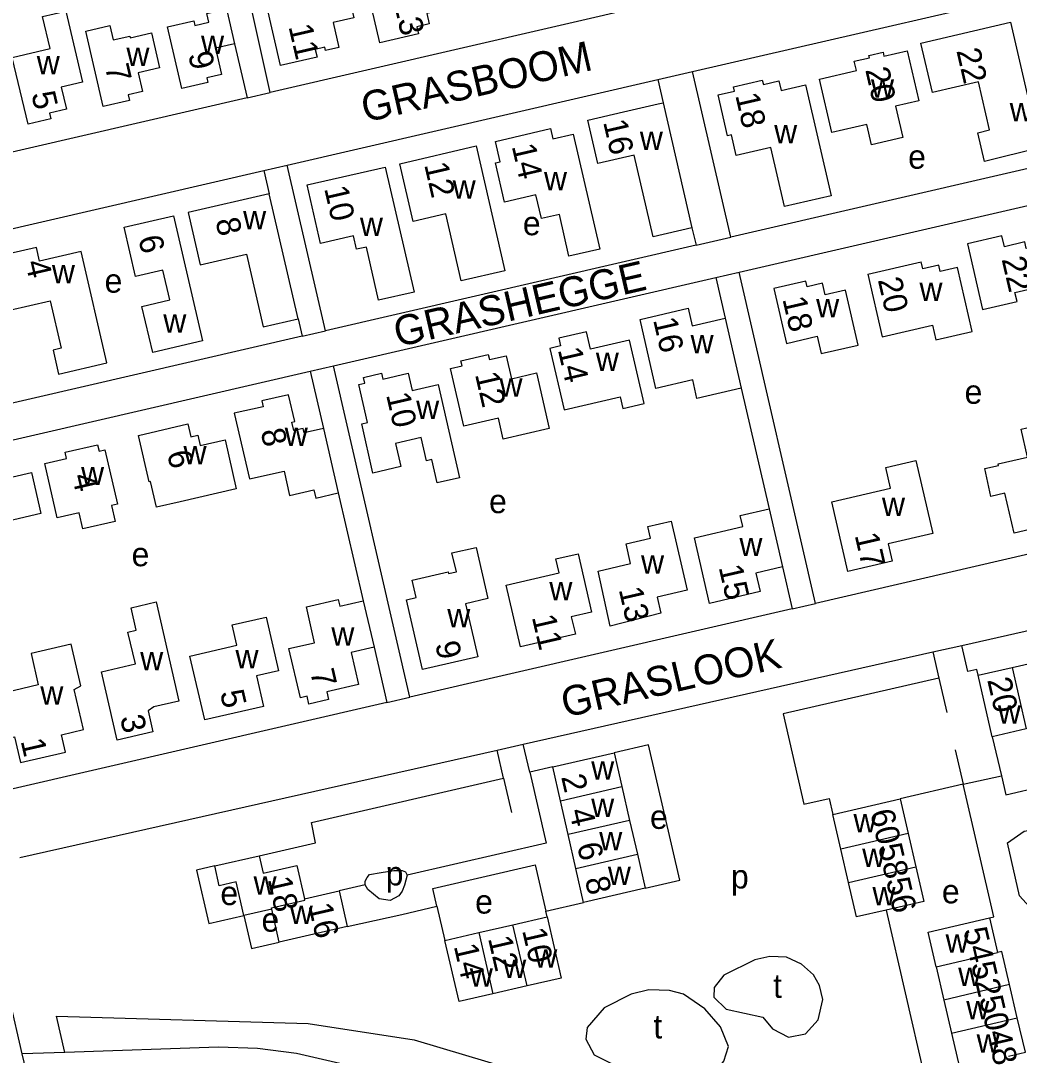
# Model space of a CAD drawing. Extents: x 155696 to 157795, y 382328 to 384028.
# Drawn here: x 157117.5 to 157284.9, y 383139.6 to 383313 of the extents above; entities that cross this region are included whole.
import ezdxf

# ---------------------------------------------------------------- set-up
doc = ezdxf.new("R2010")
doc.units = 0
for name, color, linetype in [('BLT_Basislijn', 7, 'Continuous'), ('BLT_Bebouwing', 7, 'Continuous'), ('BLT_Centroide', 7, 'Continuous'), ('BLT_Huisnummer', 7, 'Continuous'), ('BLT_Huisnummer_ tussenligend', 7, 'Continuous'), ('BLT_Onderverdeling_panden', 7, 'Continuous'), ('BLT_Straatnaam', 7, 'Continuous')]:
    doc.layers.add(name, color=color, linetype=linetype)

msp = doc.modelspace()

# ---------------------------------------------------------------- linework, layer by layer
at = {"layer": 'BLT_Basislijn'}
for p, q in [((157224.34, 383303.11), (157230.18, 383304.46)), ((157155.49, 383300.03), (157159.39, 383300.93)), ((157158.3, 383287.85), (157162.2, 383288.76)), ((157230.75, 383275.34), (157236.6, 383276.69)), ((157234.05, 383269.94), (157237.95, 383270.84)), ((157164.72, 383260.09), (157168.62, 383260.99)), ((157166.07, 383254.24), (157169.96, 383255.14)), ((157246.88, 383214.4), (157250.77, 383215.3)), ((157275.31, 383208.27), (157300.88, 383214.03)), ((157270.44, 383207.17), (157275.31, 383208.27)), ((157276.32, 383203.89), (157275.31, 383208.27)), ((157201.79, 383191.71), (157270.44, 383207.17)), ((157270.44, 383207.17), (157271.45, 383202.77)), ((157277.81, 383204.24), (157276.32, 383203.89)), ((157278.04, 383203.25), (157277.81, 383204.24)), ((157271.45, 383202.77), (157245.33, 383196.77)), ((157271.45, 383202.77), (157272.77, 383197.01)), ((157178.9, 383198.7), (157182.79, 383199.6)), ((157245.33, 383196.77), (157248.8, 383181.66)), ((157197.4, 383190.72), (157201.79, 383191.71)), ((157202.87, 383187), (157201.79, 383191.71)), ((157280.41, 383192.96), (157281.93, 383186.38)), ((157117.41, 383172.7), (157197.4, 383190.72)), ((157198.49, 383185.99), (157197.4, 383190.72)), ((157222.8, 383191.61), (157217, 383190.27)), ((157228.02, 383168.9), (157222.8, 383191.61)), ((157274.21, 383190.74), (157275.53, 383184.98)), ((157282.65, 383183.23), (157305.41, 383188.47)), ((157206.73, 383187.89), (157202.87, 383187)), ((157166.27, 383178.58), (157198.49, 383185.99)), ((157198.49, 383185.99), (157199.81, 383180.23)), ((157275.53, 383184.98), (157264.98, 383182.54)), ((157275.53, 383184.98), (157281.93, 383186.38)), ((157280.66, 383162.77), (157275.53, 383184.98)), ((157281.93, 383186.38), (157282.65, 383183.23)), ((157248.8, 383181.66), (157253.05, 383182.63)), ((157253.05, 383182.63), (157253.67, 383179.91)), ((157166.95, 383175.19), (157166.27, 383178.58)), ((157157.52, 383173.02), (157166.95, 383175.19)), ((157150.07, 383171.3), (157147.03, 383170.61)), ((157186.63, 383167.53), (157203.76, 383171.49)), ((157203.76, 383171.49), (157205.55, 383163.72)), ((157147.03, 383170.61), (157149.09, 383161.66)), ((157175.3, 383168.14), (157170.91, 383167.13)), ((157187.32, 383164.54), (157186.63, 383167.53)), ((157222.23, 383167.57), (157228.02, 383168.9)), ((157117.82, 383139.81), (157111.96, 383165.17)), ((157181.41, 383163.18), (157187.32, 383164.54)), ((157187.32, 383164.54), (157188.64, 383158.81)), ((157205.55, 383163.72), (157211.91, 383165.18)), ((157262.64, 383163.9), (157269.01, 383136.17)), ((157149.09, 383161.66), (157154.94, 383163)), ((157154.94, 383163), (157156.22, 383157.44)), ((157172.3, 383161.13), (157181.41, 383163.18)), ((157205.77, 383162.76), (157205.55, 383163.72)), ((157279.91, 383162.6), (157280.66, 383162.77)), ((157156.22, 383157.44), (157160.89, 383158.52)), ((157124.94, 383140.05), (157123.54, 383146.13)), ((157124.94, 383140.05), (157117.82, 383139.81)), ((157118.96, 383134.84), (157117.82, 383139.81))]:
    msp.add_line(p, q, dxfattribs=at)
for points in [[(157214.18, 383354.66), (157223.47, 383315.74), (157159.39, 383300.93), (157151.43, 383336.7)], [(157230.18, 383304.46), (157302.05, 383321.06)], [(157153.4, 383309.09), (157155.49, 383300.03), (157091.41, 383285.23)], [(157236.6, 383276.69), (157230.18, 383304.46)], [(157162.2, 383288.75), (157224.34, 383303.11), (157225.24, 383299.21)], [(157308.46, 383293.29), (157236.6, 383276.69)], [(157230.07, 383278.26), (157230.75, 383275.34), (157168.62, 383260.99), (157162.2, 383288.75)], [(157094.22, 383273.05), (157158.3, 383287.85), (157159.21, 383283.96)], [(157237.95, 383270.84), (157309.81, 383287.44)], [(157169.96, 383255.14), (157234.05, 383269.94)], [(157234.05, 383269.94), (157235.62, 383263.12)], [(157250.77, 383215.3), (157237.95, 383270.84)], [(157164.04, 383263.01), (157164.72, 383260.09), (157100.64, 383245.28)], [(157101.99, 383239.44), (157166.07, 383254.24)], [(157166.07, 383254.24), (157168.28, 383244.63)], [(157245.26, 383221.42), (157246.88, 383214.4), (157182.79, 383199.6), (157169.96, 383255.14)], [(157238.34, 383251.37), (157243.01, 383231.15)], [(157170.77, 383233.83), (157174.96, 383215.75)], [(157322.64, 383231.91), (157250.77, 383215.3)], [(157176.79, 383207.96), (157178.9, 383198.7)], [(157178.9, 383198.7), (157114.81, 383183.9)], [(157202.87, 383187), (157205.61, 383175.11), (157182.32, 383169.75)], [(157284.98, 383166.29), (157282.93, 383175.16), (157285.75, 383177.1), (157287.16, 383177.36), (157290.54, 383176.56), (157293.33, 383173.77), (157293.92, 383171.91), (157293.52, 383166.12), (157292.67, 383164.35), (157290.49, 383162.88), (157287.76, 383163.22), (157284.98, 383166.29)], [(157175.3, 383168.14), (157175.3, 383168.75), (157175.6, 383169.38), (157176.04, 383169.85), (157177.98, 383170.22), (157180.09, 383170.53), (157181.51, 383170.52), (157182.04, 383170.29), (157182.32, 383169.75)], [(157182.32, 383169.75), (157181.89, 383168.1), (157181.5, 383167.08), (157180.96, 383166.3), (157179.46, 383165.52), (157177.62, 383165.76), (157175.72, 383167.33), (157175.3, 383168.14)], [(157123.54, 383146.13), (157165.71, 383144.89), (157183.5, 383142.13), (157200.18, 383137.2), (157235.58, 383131.54), (157251.21, 383129.94), (157257.67, 383129.07), (157261.63, 383127.15), (157269.74, 383120.29), (157297.41, 383095.23)], [(157250.28, 383126.07), (157247.36, 383126.69), (157243.18, 383127.21), (157231.56, 383128.31), (157202.23, 383131.88), (157178.54, 383136.45), (157163.78, 383139.88), (157157.25, 383140.71), (157150.71, 383140.93), (157124.94, 383140.05)]]:
    msp.add_lwpolyline(points, dxfattribs=at)
for points in [[(157240.61, 383155.57), (157235.42, 383152.97), (157233.77, 383150.95), (157233.71, 383149.28), (157235.81, 383147.32), (157241.93, 383145.94), (157243.58, 383143.97), (157246.22, 383142.6), (157249.07, 383143.16), (157251.22, 383145.52), (157252, 383148.92), (157251.46, 383151.24), (157250.44, 383153.05), (157248.42, 383154.82), (157245.92, 383156.01), (157243.12, 383156.13)], [(157219.89, 383149.81), (157215.36, 383147.52), (157212.51, 383144.21), (157212.26, 383142.24), (157213.7, 383139.62), (157217.27, 383137.84), (157234.11, 383136.97), (157235.38, 383138.55), (157236.21, 383141.05), (157234.84, 383144.33), (157232.22, 383147.37), (157228.65, 383149.81), (157226.3, 383150.41), (157222.81, 383150.53)]]:
    msp.add_lwpolyline(points, close=True, dxfattribs=at)
at = {"layer": 'BLT_Bebouwing'}
for p, q in [((157259.53, 383270.48), (157268.46, 383272.54)), ((157259.53, 383270.48), (157261.96, 383259.97)), ((157212.39, 383260.83), (157207.74, 383259.76)), ((157207.74, 383259.76), (157208.05, 383258.45)), ((157213.07, 383257.91), (157212.39, 383260.83)), ((157219.6, 383259.42), (157213.07, 383257.91)), ((157222.05, 383248.78), (157219.6, 383259.42)), ((157208.05, 383258.45), (157206.25, 383258.03)), ((157218.02, 383249.9), (157218.47, 383247.95)), ((157218.47, 383247.95), (157222.05, 383248.78)), ((157283.75, 383204.56), (157289.44, 383205.87)), ((157278.04, 383203.25), (157283.75, 383204.56)), ((157280.41, 383192.96), (157278.04, 383203.25)), ((157286.1, 383194.27), (157280.41, 383192.96)), ((157206.73, 383187.89), (157217, 383190.27)), ((157217, 383190.27), (157218.31, 383184.6)), ((157208.02, 383182.23), (157206.73, 383187.89)), ((157218.31, 383184.6), (157219.62, 383178.92)), ((157209.32, 383176.55), (157208.02, 383182.23)), ((157253.67, 383179.91), (157264.98, 383182.54)), ((157264.98, 383182.54), (157266.31, 383176.74)), ((157255.02, 383174.11), (157253.67, 383179.91)), ((157219.62, 383178.92), (157220.92, 383173.25)), ((157210.62, 383170.87), (157209.32, 383176.55)), ((157266.31, 383176.74), (157267.59, 383171.17)), ((157150.07, 383171.3), (157157.52, 383173.02)), ((157157.52, 383173.02), (157158.2, 383170.08)), ((157220.92, 383173.25), (157222.23, 383167.57)), ((157256.31, 383168.55), (157255.02, 383174.11)), ((157150.82, 383167.97), (157150.07, 383171.3)), ((157158.2, 383170.08), (157163.85, 383171.37)), ((157163.85, 383171.37), (157165.14, 383165.81)), ((157211.91, 383165.18), (157210.62, 383170.87)), ((157267.59, 383171.17), (157268.93, 383165.34)), ((157153.65, 383168.62), (157150.82, 383167.97)), ((157154.94, 383163), (157153.65, 383168.62)), ((157222.23, 383167.57), (157211.91, 383165.18)), ((157257.65, 383162.76), (157256.31, 383168.55)), ((157165.14, 383165.81), (157170.91, 383167.13)), ((157170.91, 383167.13), (157172.3, 383161.13)), ((157159.63, 383164.08), (157154.94, 383163)), ((157160.89, 383158.52), (157159.63, 383164.08)), ((157262.64, 383163.9), (157257.65, 383162.76)), ((157268.93, 383165.34), (157262.64, 383163.9)), ((157200.06, 383161.45), (157205.77, 383162.76)), ((157205.77, 383162.76), (157208.15, 383152.51)), ((157269.63, 383160.21), (157279.91, 383162.6)), ((157279.91, 383162.6), (157281.26, 383156.8)), ((157172.3, 383161.13), (157160.89, 383158.52)), ((157194.35, 383160.13), (157200.06, 383161.45)), ((157188.64, 383158.81), (157194.35, 383160.13)), ((157191.02, 383148.55), (157188.64, 383158.81)), ((157270.98, 383154.4), (157269.63, 383160.21)), ((157270.98, 383154.4), (157272.27, 383148.81)), ((157208.15, 383152.51), (157202.42, 383151.19)), ((157202.42, 383151.19), (157196.71, 383149.87)), ((157284.59, 383145.86), (157283.29, 383151.41)), ((157196.71, 383149.87), (157191.02, 383148.55)), ((157272.27, 383148.81), (157273.55, 383143.27)), ((157285.95, 383140.08), (157284.59, 383145.86)), ((157273.55, 383143.27), (157274.89, 383137.52)), ((157283.14, 383139.43), (157285.95, 383140.08))]:
    msp.add_line(p, q, dxfattribs=at)
for points in [[(157161.12, 383305.44), (157158.69, 383315.93), (157163.95, 383317.14), (157163.67, 383318.32), (157165.82, 383318.82), (157164.83, 383323.11), (157167.08, 383323.63), (157165.25, 383331.54), (157168.99, 383332.4), (157173.37, 383313.46), (157169.94, 383312.67), (157170.9, 383308.49), (157168.66, 383307.97), (157168.54, 383308.51), (157166.92, 383308.13), (157167.22, 383306.85)], [(157175.22, 383320.09), (157179.46, 383321.07), (157178.64, 383324.59), (157187.22, 383326.57), (157189.85, 383315.15), (157185.61, 383314.18), (157186.02, 383312.42), (157183.97, 383311.95), (157184.24, 383310.78), (157177.72, 383309.27)], [(157116.12, 383306.82), (157122.48, 383308.3), (157121.22, 383313.67), (157125.12, 383314.58), (157127.91, 383302.65), (157124.35, 383301.82), (157125.22, 383298.12), (157122.38, 383297.45), (157122.59, 383296.52), (157118.81, 383295.64)], [(157128.45, 383311.24), (157132.51, 383312.17), (157133.07, 383309.74), (157135.84, 383310.38), (157135.9, 383310.08), (157139.46, 383310.91), (157140.81, 383305.06), (157137.26, 383304.24), (157137.98, 383301.12), (157135.54, 383300.56), (157135.76, 383299.58), (157131.38, 383298.57)], [(157268.44, 383309.22), (157283.45, 383312.73), (157288.32, 383291.64), (157279.1, 383289.38), (157277.98, 383294.2), (157279.96, 383294.66), (157278.08, 383302.72), (157270.37, 383300.93)], [(157251.43, 383303.18), (157257.65, 383304.62), (157257.28, 383306.17), (157259.83, 383306.76), (157259.74, 383307.15), (157262.1, 383307.71), (157262.25, 383307.02), (157266.15, 383307.93), (157268.09, 383299.54), (157264.19, 383298.63), (157265.41, 383293.38), (157260.15, 383292.17), (157259.37, 383295.58), (157253.49, 383294.22)], [(157234.45, 383300.52), (157237.22, 383301.16), (157237.04, 383301.91), (157241.86, 383303.02), (157242.03, 383302.28), (157244.62, 383302.88), (157244.99, 383301.25), (157249.08, 383302.2), (157253.38, 383283.62), (157245.55, 383281.81), (157243.26, 383291.71), (157237.47, 383290.39), (157236.69, 383293.83), (157236.03, 383293.67)], [(157197.13, 383292.73), (157206.34, 383294.88), (157206.74, 383293.17), (157210.18, 383293.97), (157214.61, 383274.69), (157209.43, 383273.51), (157207.85, 383280.5), (157204.84, 383279.82), (157203.92, 383283.8), (157198.66, 383282.58), (157197.14, 383289.15), (157197.91, 383289.33)], [(157181.08, 383288.99), (157193.87, 383291.97), (157198.71, 383271.03), (157191.39, 383269.34), (157188.8, 383280.58), (157183.32, 383279.3)], [(157165.54, 383285.44), (157178.62, 383288.43), (157183.48, 383267.47), (157177.53, 383266.1), (157175.49, 383275.03), (157173.83, 383274.66), (157173.32, 383276.91), (157167.78, 383275.64)], [(157137.88, 383265.09), (157142.55, 383266.18), (157141.39, 383271.17), (157136.77, 383270.1), (157134.9, 383278.35), (157143.18, 383280.25), (157148.01, 383259.31), (157139.68, 383257.37)], [(157278.78, 383264.55), (157284.56, 383265.88), (157284.21, 383267.39), (157293.43, 383269.51), (157291.89, 383276.15), (157286.11, 383274.81), (157285.86, 383275.88), (157282.43, 383275.09), (157282.01, 383276.91), (157276.23, 383275.58)], [(157191.34, 383255.97), (157195.93, 383257.03), (157196.13, 383256.18), (157198.92, 383256.82), (157199.81, 383252.96), (157203.99, 383253.93), (157206.14, 383244.61), (157198.44, 383242.83), (157197.62, 383246.37), (157191.83, 383245.03), (157189.6, 383254.67), (157191.53, 383255.11)], [(157187.5, 383251.98), (157191.09, 383236.36), (157187.36, 383235.5), (157186.46, 383239.41), (157185.57, 383239.21), (157184.67, 383243.12), (157180.4, 383242.13), (157181.29, 383238.23), (157176.6, 383237.15), (157174.72, 383245.39), (157175.68, 383245.61), (157174.23, 383252), (157175.22, 383252.22), (157175, 383253.19), (157178, 383253.89), (157178.23, 383252.91), (157182.5, 383253.91), (157183.18, 383250.99)], [(157137.32, 383243.47), (157145.58, 383245.38), (157146.07, 383243.2), (157147.23, 383243.48), (157147.63, 383241.75), (157151.8, 383242.7), (157153.69, 383234.5), (157144.29, 383232.34), (157140.3, 383231.42), (157139.31, 383235.72), (157139.11, 383235.67)], [(157124.98, 383240.64), (157130.44, 383241.9), (157130.69, 383240.83), (157131.65, 383241.06), (157133.75, 383231.95), (157132.79, 383231.73), (157133.41, 383229.05), (157127.95, 383227.79), (157127.33, 383230.47), (157123.69, 383229.63), (157121.59, 383238.73), (157125.23, 383239.57)], [(157105.21, 383236.12), (157112.6, 383237.83), (157113.07, 383235.8), (157119.34, 383237.24), (157120.9, 383230.37), (157107.29, 383227.19)], [(157216.37, 383211.46), (157214.32, 383220.72), (157219.79, 383221.98), (157219.02, 383225.3), (157223.09, 383226.25), (157222.65, 383228.17), (157226.6, 383229.09), (157229.27, 383217.52), (157224.24, 383216.36), (157224.85, 383213.68)], [(157184.92, 383204.2), (157182.22, 383215.89), (157183.81, 383216.28), (157183.14, 383219.21), (157189.19, 383220.59), (157189.25, 383220.29), (157190.59, 383220.6), (157189.83, 383223.76), (157193.87, 383224.7), (157195.85, 383216.1), (157192.12, 383215.24), (157194.18, 383206.34)], [(157201.32, 383208), (157198.93, 383218.35), (157207.81, 383220.41), (157207.27, 383222.75), (157211, 383223.6), (157213.25, 383213.83), (157209.84, 383213.04), (157210.52, 383210.12)], [(157133.73, 383192.38), (157131.09, 383203.83), (157136.77, 383205.15), (157135.53, 383210.5), (157136.92, 383210.83), (157136.06, 383214.58), (157140.23, 383215.54), (157144.06, 383198.94), (157139.89, 383197.97), (157138.91, 383197.3), (157139.72, 383193.76)], [(157117.52, 383188.64), (157125.06, 383190.39), (157124.39, 383193.3), (157128.05, 383194.14), (157126.49, 383200.86), (157127.62, 383201.48), (157126.02, 383208.45), (157119.28, 383206.9), (157120.5, 383201.63), (157113.65, 383200.05), (157115.36, 383192.65), (157116.53, 383192.92)]]:
    msp.add_lwpolyline(points, close=True, dxfattribs=at)
for points in [[(157153.4, 383309.09), (157150.18, 383308.35), (157151.19, 383303.97), (157148.76, 383303.4), (157148.94, 383302.62), (157144.55, 383301.61), (157142.17, 383311.94), (157146.55, 383312.95), (157146.73, 383312.17), (157149.07, 383312.71), (157148.73, 383314.17), (157152.05, 383314.94)], [(157152.05, 383314.94), (157153.4, 383309.09)], [(157212.6, 383296.29), (157218.59, 383297.67), (157224.39, 383299.01), (157225.24, 383299.21)], [(157225.24, 383299.21), (157230.07, 383278.26)], [(157223.55, 383276.75), (157220.39, 383290.42), (157214.28, 383289.01), (157212.6, 383296.29)], [(157159.21, 383283.96), (157145.61, 383280.82), (157147.64, 383272.05), (157155.38, 383273.84), (157158.2, 383261.66), (157164.04, 383263.01)], [(157164.04, 383263.01), (157159.21, 383283.96)], [(157230.07, 383278.26), (157223.55, 383276.75)], [(157127.69, 383274.26), (157120.73, 383272.66), (157120.2, 383274.95), (157113.57, 383273.42), (157115.65, 383264.45), (157122.5, 383266.04), (157124.35, 383258.07), (157122.98, 383257.75), (157123.91, 383253.74), (157132, 383255.61), (157127.69, 383274.26)], [(157261.96, 383259.97), (157270.37, 383261.91), (157270.93, 383259.46), (157277.03, 383260.87), (157274.56, 383271.58), (157271.66, 383270.91), (157271.42, 383271.98), (157268.74, 383271.37), (157268.46, 383272.54)], [(157243.78, 383268.09), (157245.91, 383258.88), (157251.06, 383260.07), (157251.72, 383257.17), (157257.93, 383258.61), (157255.8, 383267.81), (157252.37, 383267.02), (157251.93, 383268.95), (157249.36, 383268.36), (157249.13, 383269.32), (157243.78, 383268.09)], [(157238.34, 383251.37), (157230.9, 383249.65), (157230.19, 383252.76), (157224.03, 383251.34), (157221.36, 383262.91), (157229.44, 383264.77), (157230.12, 383261.85), (157235.62, 383263.12)], [(157235.62, 383263.12), (157238.34, 383251.37)], [(157206.25, 383258.03), (157208.62, 383247.73), (157218.02, 383249.9)], [(157168.28, 383244.63), (157165.05, 383243.89), (157164.89, 383244.64), (157163.32, 383244.27), (157162.99, 383245.67), (157163.5, 383245.79), (157162.46, 383250.27), (157157.96, 383249.25), (157158.18, 383248.27), (157153.35, 383247.18), (157155.88, 383236.16), (157161.69, 383237.49), (157162.63, 383233.41), (157166.71, 383234.36), (157167.03, 383232.96), (157170.77, 383233.83)], [(157284.07, 383227.1), (157282.53, 383233.76), (157280.16, 383233.24), (157279.13, 383237.93), (157281.47, 383238.41), (157281.4, 383238.67), (157286.33, 383239.81), (157285.24, 383244.52), (157292.84, 383246.28), (157295.49, 383234.82), (157291.31, 383233.85)], [(157168.28, 383244.63), (157170.77, 383233.83)], [(157263.37, 383234.61), (157262.57, 383238.07), (157267.6, 383239.23), (157270.42, 383227.03), (157262.93, 383225.3)], [(157256.22, 383220.67), (157253.52, 383232.34), (157263.37, 383234.61)], [(157291.31, 383233.85), (157292.42, 383229.03), (157284.07, 383227.1)], [(157245.26, 383221.42), (157240.77, 383220.38), (157241.49, 383217.27), (157233.03, 383215.31), (157230.49, 383226.31), (157238.57, 383228.18), (157238.15, 383230.03), (157243.01, 383231.15)], [(157243.01, 383231.15), (157245.26, 383221.42)], [(157262.93, 383225.3), (157263.6, 383222.37), (157256.22, 383220.67)], [(157176.79, 383207.96), (157172.92, 383207.07), (157174.17, 383201.72), (157168.88, 383200.49), (157169.17, 383199.2), (157165.87, 383198.44), (157165.59, 383199.73), (157164.43, 383199.46), (157162.5, 383207.72), (157166.82, 383208.72), (157165.43, 383214.72), (157170.79, 383215.97), (157171.05, 383214.84), (157174.96, 383215.75)], [(157174.96, 383215.75), (157176.79, 383207.96)], [(157145.91, 383206.48), (157153.77, 383208.29), (157152.99, 383211.7), (157158.7, 383213.02), (157160.78, 383204.02)], [(157160.78, 383204.02), (157157.06, 383203.16), (157158.25, 383198.04), (157148.39, 383195.76), (157145.91, 383206.48)], [(157283.29, 383151.41), (157281.98, 383156.97), (157281.26, 383156.8)]]:
    msp.add_lwpolyline(points, dxfattribs=at)
at = {"layer": 'BLT_Onderverdeling_panden'}
for p, q in [((157283.75, 383204.56), (157286.1, 383194.27)), ((157208.02, 383182.23), (157218.31, 383184.6)), ((157219.62, 383178.92), (157209.32, 383176.55)), ((157266.31, 383176.74), (157255.02, 383174.11)), ((157210.62, 383170.87), (157220.92, 383173.25)), ((157256.31, 383168.55), (157267.59, 383171.17)), ((157202.42, 383151.19), (157200.06, 383161.45)), ((157194.35, 383160.13), (157196.71, 383149.87)), ((157270.98, 383154.4), (157281.26, 383156.8)), ((157283.29, 383151.41), (157272.27, 383148.81)), ((157273.55, 383143.27), (157284.59, 383145.86))]:
    msp.add_line(p, q, dxfattribs=at)
msp.add_lwpolyline([(157159.63, 383164.08), (157159.58, 383164.3), (157165.19, 383165.58), (157165.14, 383165.81)], dxfattribs=at)

# ---------------------------------------------------------------- texts
at = {"layer": 'BLT_Centroide'}
for s, p in [('w', (157147.78, 383307.38)), ('w', (157135.27, 383305.38)), ('w', (157120.24, 383303.99)), ('w', (157260.07, 383300.06)), ('w', (157283.32, 383296.12)), ('w', (157221.33, 383291.3)), ('w', (157243.84, 383292.44)), ('e', (157266.3, 383288.16)), ('w', (157205.26, 383284.56)), ('w', (157189.95, 383283.14)), ('w', (157154.83, 383278)), ('e', (157201.72, 383277.01)), ('w', (157174.41, 383276.91)), ('w', (157122.78, 383268.97)), ('e', (157131.61, 383267.38)), ('w', (157268.2, 383266)), ('w', (157250.88, 383263.25)), ('w', (157141.45, 383260.67)), ('w', (157229.83, 383257.22)), ('w', (157213.95, 383254.28)), ('w', (157197.8, 383249.94)), ('e', (157275.76, 383248.76)), ('w', (157183.84, 383246.22)), ('w', (157161.81, 383241.66)), ('w', (157144.84, 383238.59)), ('w', (157127.67, 383235.12)), ('e', (157196.06, 383230.43)), ('w', (157261.91, 383229.94)), ('e', (157136.14, 383221.53)), ('w', (157238.02, 383223.22)), ('w', (157221.53, 383220.28)), ('w', (157206.16, 383215.81)), ('w', (157189.05, 383211.31)), ('w', (157169.62, 383208.22)), ('w', (157153.55, 383204.41)), ('w', (157137.58, 383204.09)), ('w', (157120.84, 383198.33)), ('w', (157281.34, 383195.16)), ('w', (157213.17, 383185.78)), ('w', (157213.17, 383179.51)), ('e', (157223.03, 383177.51)), ('w', (157257.14, 383176.93)), ('w', (157214.52, 383173.92)), ('w', (157258.59, 383171.14)), ('p', (157178.73, 383168.04)), ('w', (157215.97, 383168.13)), ('w', (157156.58, 383166.49)), ('p', (157236.6, 383167.52)), ('e', (157151.02, 383164.74)), ('w', (157260.32, 383164.68)), ('e', (157271.96, 383165.03)), ('e', (157193.72, 383163.31)), ('w', (157162.65, 383161.57)), ('e', (157157.91, 383160.28)), ('w', (157272.57, 383156.77)), ('w', (157203.63, 383154.24)), ('w', (157198.42, 383152.51)), ('w', (157192.83, 383151.06)), ('w', (157274.69, 383151.18)), ('t', (157243.67, 383149.18)), ('w', (157276.04, 383145.59)), ('t', (157223.6, 383142.39)), ('w', (157277.78, 383139.99))]:
    msp.add_text(s, height=4, dxfattribs=at).set_placement(p)
at = {"layer": 'BLT_Huisnummer'}
for s, rotation, p in [('13', 283.0062, (157180.05, 383316)), ('11', 283.0062, (157162.42, 383311.99)), ('9', 283.0062, (157145.59, 383307.36)), ('22', 283.0062, (157274.37, 383307.95)), ('7', 283.0057, (157131.65, 383305.27)), ('20', 283.0067, (157259.09, 383304.75)), ('5', 282.9958, (157119.31, 383300.7)), ('18', 283.0059, (157237.31, 383300.47)), ('16', 283.0098, (157215.16, 383296)), ('14', 283.0032, (157199.84, 383291.94)), ('12', 283.0098, (157185.17, 383288.84)), ('10', 283.0057, (157168.4, 383284.87)), ('8', 283.0064, (157150.16, 383279.51)), ('6', 283.0071, (157137.23, 383276.57)), ('22', 283.0062, (157281.95, 383273.01)), ('4', 283.0066, (157118.3, 383272.46)), ('20', 283.0045, (157261.2, 383269.54)), ('18', 283.0064, (157245.21, 383266.33)), ('16', 283.0082, (157223.54, 383262.83)), ('14', 283.0064, (157207.57, 383257.82)), ('12', 283.0064, (157193.68, 383253.7)), ('10', 283.0083, (157178.78, 383250.26)), ('8', 283.0064, (157157.73, 383244.19)), ('6', 283.007, (157142.05, 383240.53)), ('4', 283.0064, (157126.12, 383236.66)), ('17', 283.0104, (157257.32, 383226.74)), ('15', 283.0104, (157234.52, 383221.37)), ('13', 283.0104, (157217.77, 383217.65)), ('11', 283.0104, (157203.21, 383213.02)), ('9', 283.0104, (157186.99, 383208.53)), ('7', 283.0104, (157166.05, 383203.88)), ('20', 283.0104, (157279.54, 383202.48)), ('5', 283.0104, (157150.93, 383200.38)), ('3', 283.0104, (157134.17, 383196.19)), ('1', 283.0104, (157117.52, 383192.26)), ('2', 283.0104, (157208.12, 383186.24)), ('60', 283.0104, (157259.91, 383180.38)), ('18', 283.0104, (157158.93, 383169.1)), ('8', 283.0104, (157212.09, 383169.08)), ('56', 283.0104, (157262.56, 383168.93)), ('16', 283.0104, (157165.75, 383164.67)), ('10', 283.0104, (157201.58, 383160.5)), ('54', 283.0104, (157275.51, 383160.59)), ('14', 283.0104, (157190.13, 383157.86)), ('48', 283.0104, (157279.48, 383143.41))]:
    msp.add_text(s, height=4, rotation=rotation, dxfattribs=at).set_placement(p)
at = {"layer": 'BLT_Huisnummer_ tussenligend'}
for s, p in [('4', (157209.44, 383180.54)), ('6', (157210.77, 383174.81)), ('58', (157261.24, 383174.65)), ('12', (157195.86, 383159.17)), ('52', (157276.84, 383154.85)), ('50', (157278.16, 383149.14))]:
    msp.add_text(s, height=4, rotation=283.0104, dxfattribs=at).set_placement(p)
at = {"layer": 'BLT_Straatnaam'}
for s, rotation, p in [('GRASBOOM', 13.0063, (157175.29, 383295.89)), ('GRASHEGGE', 13.007, (157180.74, 383258.24)), ('GRASLOOK', 13.0068, (157208.8, 383196.14))]:
    msp.add_text(s, height=5, rotation=rotation, dxfattribs=at).set_placement(p)

doc.saveas('drawing.dxf')
